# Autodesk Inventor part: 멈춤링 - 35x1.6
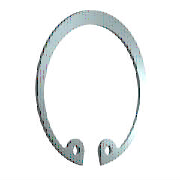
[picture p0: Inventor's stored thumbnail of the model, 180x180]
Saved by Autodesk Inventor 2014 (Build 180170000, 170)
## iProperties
IsCustomPart: 1
Created: 2015-09
Part Number: 멈춤링 - 35x1.6
Material: 강철, 연강
Description: 리테이닝 링(C형)
Document SubType Name: Modeling
Standard: KS B 1336
Designer: mduedu
Standards Organization: KS
Language: ko-KR
Size Designation: 35x1.6
Categories: <MemberInstance><Categories><Category DisplayName="샤프트 부품" InternalName="7f7aeb1f-a693-4053-b835-cee3144e0d98" Mnemonic="SHFT"><Category DisplayName="써클립" Inter
Density: 7.86 g/cm^3
Mass: 3.5371 g
Surface Area: 9.09651 cm^2
Volume: 0.450013 cm^3
Appearance: Glossy - Black
Author: mduedu
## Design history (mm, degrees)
sketch "스케치1"
  geometry: L1 (0, 15.113)-(0, -73.177) reference; L2 (-45.5, 0)-(45.5, 0) reference; L3 (-4.964, 1)-(1.502, 1); L4 (0, -2.5)-(-5.307, -2.5); L5 (0, -17.5)-(-8.583, -33.888); L6 (-8.583, -33.888)-(-21.772, -26.981); L7 (-7.377, -31.585)-(-17.631, -26.214); L8 (-5.162, -32.745)-(-6.29, -34.898); L9 (5.162, -32.745)-(6.29, -34.898); C1 r 1.25 at (-7.377, -31.585); C2 r 1.25 at (7.377, -31.585); A1 r 15.875 centre (0, -18.375) between (11.82, -28.972) and (-11.82, -28.972); A2 r 18.5 centre (0, -17.5) between (6.29, -34.898) and (-6.29, -34.898); A3 r 2.5 centre (-7.377, -31.585) between (-5.162, -32.745) and (-8.668, -29.444); A4 r 2.5 centre (-9.959, -27.303) between (-11.82, -28.972) and (-8.668, -29.444); A5 r 2.5 centre (9.959, -27.303) between (8.668, -29.444) and (11.82, -28.972); A6 r 2.5 centre (7.377, -31.585) between (8.668, -29.444) and (5.162, -32.745); 3 further points
  constraints: 15 point on circle, 14 end point, 9 symmetric about line, 8 centre point, 6 tangent, 4 coincident, 4 point on line, 3 perpendicular, 1 parallel, 4 other
  dimensions: "d8" = 0.875 distance of A1.centre L5.start (= 0.25 x SRB1); "d38" = 3.5 distance between parallel lines of L4 L3 (= SRB1); "d39" = 17.5 distance from line of L5.start L2 (= 0.5 x WD); "d43" = 18.5 radius of A2 (= 0.5 x ND); "d45" = 2.6 distance between parallel lines of L7 L6 (= 0.5 x SRB2); "d46" = 2.5 radius of A4 (= SD5); "d47" = 6.29 distance from line of L1 L8.end (= 0.17 x ND); "d48" = 2.5 diameter of C1 (= SD5); "d49" = 2.5 radius of A3 (= SD5)
extrude "본체" new body sketch "스케치1" distance "d2" = 1.6 (= SD); taper "d3" = 0 deg
workaxis "Work Axis1"
workaxis "Work Axis2"
workplane "Work Plane1"
body "Solid1"
other parameters: "WD" = 35 [user parameter; used in 3 equation terms], "SD" = 1.6 [user parameter; used in 1 equation term], "SRB1" = 3.5 [user parameter; used in 2 equation terms], "ND" = 37 [user parameter; used in 2 equation terms], "SRB2" = 5.2 [user parameter; used in 1 equation term], "SD5" = 2.5 [user parameter; used in 3 equation terms], "d50" = 0, "d51" = 0, "d52" = 0, "d53" = 0, "WDMIN" = 34 [user parameter], "SD6" = 37.8 [user parameter], "WDMAX" = 35 (= WD) [user parameter], "NND" = 35 (= WD) [user parameter]
